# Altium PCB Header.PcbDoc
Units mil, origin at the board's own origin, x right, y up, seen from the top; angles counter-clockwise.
Board outline 6000 x 4000 mil, 2 copper layers (Top Layer, Bottom Layer); 0 components, 0 nets, 20 pads, 0 vias.
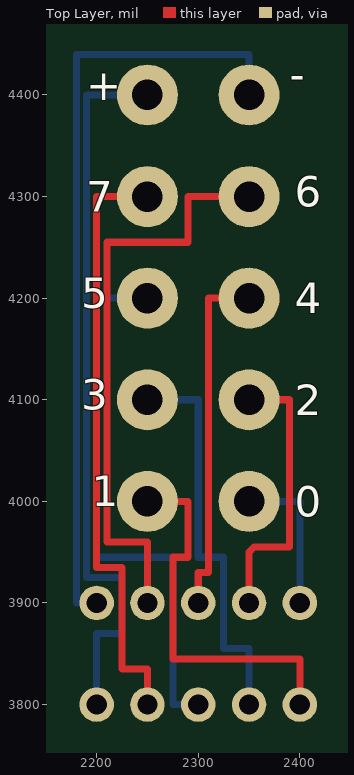
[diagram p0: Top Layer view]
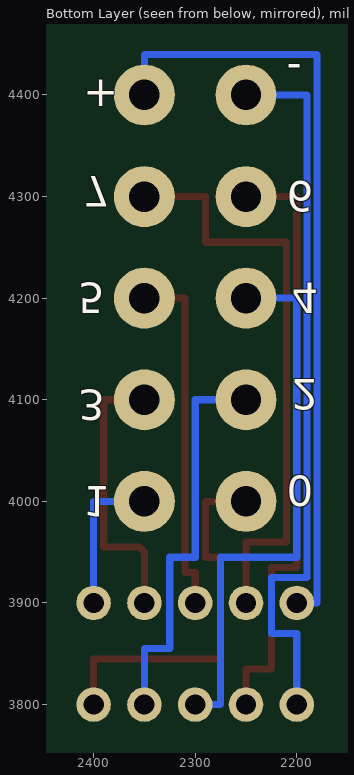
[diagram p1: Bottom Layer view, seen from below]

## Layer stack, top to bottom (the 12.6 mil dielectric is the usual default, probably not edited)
Top Layer: signal copper 1.4
Dielectric: dielectric 12.6, FR-4, Dk 4.8
Bottom Layer: signal copper 1.4

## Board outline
1000,1000 7000,1000 7000,5000 1000,5000

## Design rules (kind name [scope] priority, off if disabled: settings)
Clearance [All] p1: gap=10
ComponentClearance [All] p1: gap=10 collisioncheckmode=0
HoleSize [All] p1: absolutevalues=TRUE maxlimit=28 minlimit=20 maxpercent=80.000 minpercent=20.000
PolygonConnect [All] p1: connectstyle=Relief reliefconductorwidth=10 reliefentries=4 polygonreliefangle="90 Angle"
RoutingLayers [All] p1: top layer=Horizontal bottom layer=Vertical
RoutingVias [All] p1: holewidth=28 width=50 viastyle="Through Hole" minholewidth=28 minwidth=50 maxholewidth=28 maxwidth=50
SolderMaskExpansion [All] p1: expansion=4
TestPointUsage [All] p1: valid=0 allowmultiple=FALSE
Testpoint [All] p1: side=15 testpointundercomponent=TRUE minsize=40 maxsize=100 preferedsize=60 minholesize=0 maxholesize=40 preferedholesize=32 testpointgrid=1 style=1023 order=-539222988
Width [All] p1: maxlimit=7 minlimit=7 preferedwidth=7
15 further rules are at their usual default settings.

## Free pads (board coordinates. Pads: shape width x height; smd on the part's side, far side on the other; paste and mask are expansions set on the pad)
  round 34 hole 20: 1(2200,3800) 2(2200,3900) 3(2250,3800) 4(2250,3900) 5(2300,3800) 6(2300,3900) 7(2350,3800) 8(2350,3900) 9(2400,3800) 10(2400,3900)
  round 60 hole 30: 1(2250,4400) 2(2350,4400) 3(2250,4300) 4(2350,4300) 5(2250,4200) 6(2350,4200) 7(2250,4100) 8(2350,4100) 9(2250,4000) 10(2350,4000)

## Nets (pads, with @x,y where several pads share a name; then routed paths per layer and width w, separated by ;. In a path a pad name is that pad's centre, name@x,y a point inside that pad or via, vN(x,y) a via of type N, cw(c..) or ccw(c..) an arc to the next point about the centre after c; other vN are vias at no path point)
copper on no net: | length 4777.1
  Top Layer w7: 2250,3800 2250,3835 2225,3835 2225,3935 2200,3935 2200,4300 2250,4300 ; 2250,3900 2250,3960 2210,3960 2210,4255 2290,4255 2290,4300 2350,4300 ; 2250,4000 2290,4000 2290,3945 2275,3945 2275,3845 2400,3845 2400,3800 ; 2300,3900 2300,3930 2310,3930 2310,4200 2350,4200 ; 2350,3900 2350,3950 2355,3955 2390,3955 2390,4100 2350,4100
  Bottom Layer w7: 2200,3800 2200,3870 2225,3870 2225,3880 2225,3925 2190,3925 2190,4400 2250,4400 ; 2200,3900 2180,3900 2180,4440 2350,4440 2350,4400 ; 2250,4100 2300,4100 2300,3945 2325,3945 2325,3855 2350,3855 2350,3800 ; 2250,4200 2200,4200 2200,3945 2275,3945 2275,3800 2300,3800 ; 2350,4000 2400,4000 2400,3900

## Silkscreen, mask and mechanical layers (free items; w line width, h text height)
Top Overlay:
  text "-" at 2390,4405 h30
  text "+" at 2190,4395 h30
  text "6" at 2395,4290 h30
  text "7" at 2190,4285 h30
  text "5" at 2185,4190 h30
  text "4" at 2395,4185 h30
  text "3" at 2185,4090 h30
  text "2" at 2395,4085 h30
  text "1" at 2195,3995 h30
  text "0" at 2395,3985 h30
Bottom Overlay:
  text "-" at 2210,4440 h30 r180
  text "+" at 2410,4415 h30 r180
  text "7" at 2410,4320 h30 r180
  text "6" at 2210,4315 h30 r180
  text "4" at 2205,4215 h30 r180
  text "5" at 2415,4215 h30 r180
  text "2" at 2205,4120 h30 r180
  text "3" at 2415,4110 h30 r180
  text "0" at 2210,4025 h30 r180
  text "1" at 2410,4015 h30 r180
